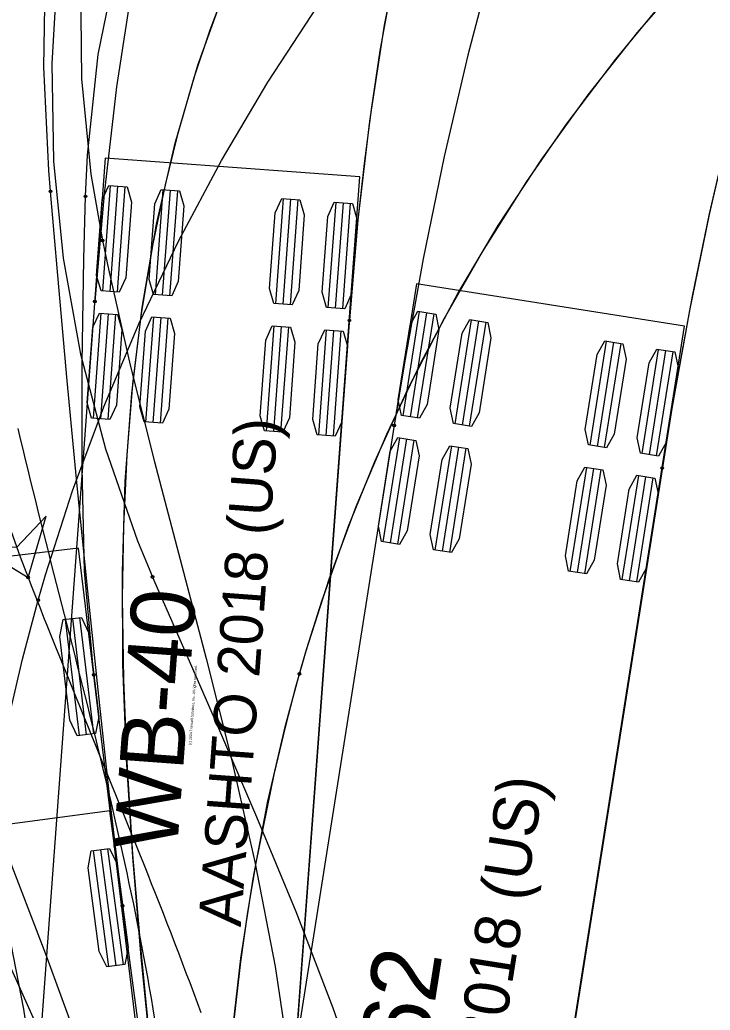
# Model space of a CAD drawing. Extents: x 1600240 to 1604759, y 285789 to 289704.
# Drawn here: x 1601627.09 to 1601648.72, y 286639.24 to 286670.26 of the extents above; entities that cross this region are included whole.
import ezdxf

# ---------------------------------------------------------------- set-up
doc = ezdxf.new("R2010")
doc.units = 0
for name, color, linetype in [('MT_P_CL_Double_Solid', 7, 'Continuous'), ('MT_X_Edge_Line', 7, 'Continuous'), ('TR_Turning_Path2', 7, 'Continuous'), ('TR_Turning_Path3', 7, 'Continuous'), ('TR_Turning_Path4', 7, 'Continuous')]:
    doc.layers.add(name, color=color, linetype=linetype)

msp = doc.modelspace()

# ---------------------------------------------------------------- linework, layer by layer
at = {"layer": 'MT_P_CL_Double_Solid'}
for p, q in [((1601629.914, 286645.489), (1601621.984, 286644.432)), ((1601630.904, 286638.054), (1601629.914, 286645.489)), ((1601629.386, 286644.241), (1601629.871, 286640.607)), ((1601629.613, 286644.272), (1601630.098, 286640.637)), ((1601629.84, 286644.302), (1601630.325, 286640.667))]:
    msp.add_line(p, q, dxfattribs=at)
for points in [[(1601628.052, 286664.891), (1601627.998, 286665.545), (1601627.842, 286668.782), (1601627.894, 286671.975), (1601628.19, 286675.107), (1601628.758, 286678.153), (1601629.625, 286681.081), (1601630.808, 286683.848), (1601632.315, 286686.434), (1601634.062, 286688.889), (1601636.008, 286691.19), (1601638.138, 286693.32), (1601640.439, 286695.265), (1601642.893, 286697.012), (1601645.484, 286698.549), (1601648.194, 286699.864), (1601651.004, 286700.949), (1601653.895, 286701.797), (1601656.846, 286702.4), (1601658.937, 286702.676)], [(1601632.426, 286627.244), (1601632.345, 286627.903), (1601631.948, 286631.194), (1601631.567, 286634.468), (1601631.211, 286637.711), (1601630.894, 286640.909), (1601630.63, 286644.047), (1601630.434, 286647.107), (1601630.321, 286650.076), (1601630.303, 286652.973), (1601630.392, 286655.803), (1601630.596, 286658.564), (1601630.923, 286661.252), (1601631.376, 286663.864), (1601631.958, 286666.395), (1601632.67, 286668.841), (1601633.512, 286671.196), (1601634.483, 286673.455), (1601635.579, 286675.612), (1601636.419, 286677.058)], [(1601633.596, 286671.411), (1601633.041, 286669.939), (1601632.543, 286668.446), (1601632.019, 286666.63), (1601631.64, 286665.099), (1601631.254, 286663.244), (1601630.894, 286661.06), (1601630.624, 286658.856), (1601630.44, 286656.637), (1601630.333, 286654.405), (1601630.297, 286652.164), (1601630.333, 286649.594), (1601630.438, 286647.019), (1601630.624, 286644.118), (1601630.866, 286641.217), (1601631.215, 286637.672), (1601631.642, 286633.807), (1601632.214, 286628.979), (1601633.671, 286617.403), (1601635.924, 286600.387), (1601627.995, 286599.33), (1601627.804, 286600.759)], [(1601630.31, 286642.515), (1601629.922, 286645.791), (1601629.563, 286649.081), (1601629.218, 286652.372), (1601628.89, 286655.664), (1601628.577, 286658.958), (1601628.279, 286662.253), (1601628.052, 286664.89)]]:
    msp.add_lwpolyline(points, dxfattribs=at)
msp.add_lwpolyline([(1601629.33, 286644.234), (1601629.897, 286644.309), (1601630.135, 286643.823), (1601630.484, 286641.206), (1601630.381, 286640.675), (1601629.814, 286640.599), (1601629.576, 286641.085), (1601629.227, 286643.702)], close=True, dxfattribs=at)
for centre in [(1601628.052, 286664.89), (1601628.052, 286664.891), (1601630.31, 286642.515)]:
    msp.add_circle(centre, 0.0417, dxfattribs=at)
at = {"layer": 'MT_X_Edge_Line'}
msp.add_arc((1602837.866, 287782.942), 1921, 229.7619, 229.7619, dxfattribs=at)
at = {"layer": 'TR_Turning_Path2'}
for p, q in [((1601629.768, 286665.929), (1601627.338, 286633.019)), ((1601637.747, 286665.34), (1601629.768, 286665.929)), ((1601635.316, 286632.43), (1601637.747, 286665.34)), ((1601629.691, 286661.774), (1601629.934, 286665.065)), ((1601629.92, 286661.757), (1601630.163, 286665.048)), ((1601630.148, 286661.74), (1601630.391, 286665.031)), ((1601631.337, 286661.652), (1601631.58, 286664.943)), ((1601631.565, 286661.635), (1601631.808, 286664.926)), ((1601631.794, 286661.618), (1601632.037, 286664.909)), ((1601635.11, 286661.373), (1601635.353, 286664.665)), ((1601635.338, 286661.357), (1601635.581, 286664.648)), ((1601635.567, 286661.34), (1601635.81, 286664.631)), ((1601636.755, 286661.252), (1601636.998, 286664.543)), ((1601636.984, 286661.235), (1601637.227, 286664.526)), ((1601637.212, 286661.218), (1601637.455, 286664.509)), ((1601629.397, 286657.784), (1601629.64, 286661.075)), ((1601629.625, 286657.768), (1601629.868, 286661.059)), ((1601629.854, 286657.751), (1601630.097, 286661.042)), ((1601631.042, 286657.663), (1601631.285, 286660.954)), ((1601631.271, 286657.646), (1601631.514, 286660.937)), ((1601631.499, 286657.629), (1601631.742, 286660.92)), ((1601634.815, 286657.384), (1601635.058, 286660.675)), ((1601635.044, 286657.367), (1601635.287, 286660.658)), ((1601635.272, 286657.351), (1601635.515, 286660.642)), ((1601636.461, 286657.263), (1601636.704, 286660.554)), ((1601636.689, 286657.246), (1601636.932, 286660.537)), ((1601636.918, 286657.229), (1601637.161, 286660.52))]:
    msp.add_line(p, q, dxfattribs=at)
for points in [[(1601660.811, 286703.245), (1601659.827, 286703.152), (1601656.594, 286702.738), (1601653.44, 286702.14), (1601650.384, 286701.326), (1601647.454, 286700.268), (1601644.684, 286698.947), (1601642.116, 286697.348), (1601639.799, 286695.471), (1601637.711, 286693.321), (1601635.814, 286690.989), (1601634.126, 286688.501), (1601632.661, 286685.877), (1601631.428, 286683.135), (1601630.438, 286680.297), (1601629.698, 286677.384), (1601629.213, 286674.418), (1601628.987, 286671.421), (1601629.021, 286668.415), (1601629.316, 286665.424), (1601629.676, 286663.351)], [(1601642.549, 286697.143), (1601641.961, 286696.515), (1601640.089, 286694.32), (1601638.357, 286691.963), (1601636.775, 286689.446), (1601635.349, 286686.773), (1601634.085, 286683.95), (1601632.985, 286680.993), (1601632.048, 286677.918), (1601631.267, 286674.746), (1601630.627, 286671.482), (1601630.119, 286668.166), (1601629.728, 286664.814), (1601629.437, 286661.441)], [(1601648.312, 286691.594), (1601647.84, 286691.09), (1601646.342, 286689.331), (1601644.957, 286687.442), (1601643.684, 286685.412), (1601642.524, 286683.234), (1601641.481, 286680.901), (1601640.559, 286678.416), (1601639.758, 286675.783), (1601639.076, 286673.011), (1601638.507, 286670.1), (1601638.047, 286667.089), (1601637.686, 286664.001), (1601637.415, 286660.852)], [(1601638.904, 286672.205), (1601638.371, 286669.291), (1601638.107, 286667.532), (1601637.879, 286665.767), (1601637.685, 286663.997), (1601637.473, 286661.627), (1601635.686, 286637.432)], [(1601621.785, 286664.025), (1601621.952, 286662.949), (1601622.604, 286659.411), (1601623.361, 286655.937), (1601624.18, 286652.522), (1601625.016, 286649.158), (1601625.826, 286645.835), (1601626.568, 286642.545), (1601627.202, 286639.282), (1601627.69, 286636.036), (1601628.097, 286632.743), (1601628.475, 286629.447), (1601628.824, 286626.147), (1601629.142, 286622.845)], [(1601629.677, 286663.347), (1601629.863, 286662.452), (1601630.549, 286659.447), (1601631.309, 286656.419), (1601632.111, 286653.36), (1601632.926, 286650.258), (1601633.718, 286647.104), (1601634.452, 286643.89), (1601635.091, 286640.609), (1601635.595, 286637.259), (1601636.013, 286633.896), (1601636.401, 286630.529), (1601636.759, 286627.159), (1601637.086, 286623.785)], [(1601627.026, 286657.463), (1601627.103, 286657.139), (1601627.181, 286656.815), (1601627.259, 286656.491), (1601627.338, 286656.167), (1601627.417, 286655.843), (1601627.497, 286655.519), (1601627.577, 286655.196), (1601627.658, 286654.872), (1601627.739, 286654.549), (1601627.82, 286654.226), (1601627.902, 286653.903), (1601627.983, 286653.579), (1601628.066, 286653.256), (1601628.148, 286652.933), (1601628.23, 286652.61), (1601628.313, 286652.287), (1601628.395, 286651.964), (1601628.478, 286651.642), (1601628.561, 286651.319), (1601628.643, 286650.996), (1601628.726, 286650.673), (1601628.808, 286650.35), (1601628.89, 286650.027), (1601628.972, 286649.704), (1601629.054, 286649.38), (1601629.135, 286649.057), (1601629.216, 286648.734), (1601629.297, 286648.41), (1601629.378, 286648.087), (1601629.458, 286647.763), (1601629.537, 286647.44), (1601629.616, 286647.116), (1601629.695, 286646.792), (1601629.772, 286646.468), (1601629.85, 286646.143), (1601629.926, 286645.819), (1601630.002, 286645.495), (1601630.077, 286645.17), (1601630.152, 286644.845), (1601630.225, 286644.52), (1601630.298, 286644.194), (1601630.37, 286643.869), (1601630.441, 286643.543), (1601630.51, 286643.217), (1601630.579, 286642.891), (1601630.647, 286642.565), (1601630.714, 286642.238), (1601630.779, 286641.911), (1601630.844, 286641.584), (1601630.907, 286641.257), (1601630.969, 286640.929), (1601631.03, 286640.602), (1601631.089, 286640.274), (1601631.147, 286639.945), (1601631.203, 286639.617), (1601631.258, 286639.288), (1601631.312, 286638.959)]]:
    msp.add_lwpolyline(points, dxfattribs=at)
for points in [[(1601630.205, 286661.736), (1601629.635, 286661.778), (1601629.497, 286662.251), (1601629.672, 286664.621), (1601629.878, 286665.069), (1601630.448, 286665.027), (1601630.586, 286664.553), (1601630.411, 286662.184)], [(1601631.851, 286661.614), (1601631.28, 286661.656), (1601631.142, 286662.13), (1601631.317, 286664.499), (1601631.523, 286664.947), (1601632.094, 286664.905), (1601632.231, 286664.432), (1601632.056, 286662.062)], [(1601635.624, 286661.336), (1601635.053, 286661.378), (1601634.915, 286661.851), (1601635.09, 286664.221), (1601635.296, 286664.669), (1601635.867, 286664.627), (1601636.004, 286664.153), (1601635.83, 286661.784)], [(1601637.269, 286661.214), (1601636.699, 286661.256), (1601636.561, 286661.73), (1601636.736, 286664.099), (1601636.942, 286664.547), (1601637.512, 286664.505), (1601637.65, 286664.032), (1601637.475, 286661.662)], [(1601629.91, 286657.747), (1601629.34, 286657.789), (1601629.202, 286658.262), (1601629.377, 286660.632), (1601629.583, 286661.08), (1601630.153, 286661.038), (1601630.291, 286660.564), (1601630.116, 286658.195)], [(1601631.556, 286657.625), (1601630.986, 286657.667), (1601630.848, 286658.141), (1601631.023, 286660.51), (1601631.229, 286660.958), (1601631.799, 286660.916), (1601631.937, 286660.443), (1601631.762, 286658.073)], [(1601635.329, 286657.346), (1601634.759, 286657.389), (1601634.621, 286657.862), (1601634.796, 286660.231), (1601635.002, 286660.68), (1601635.572, 286660.637), (1601635.71, 286660.164), (1601635.535, 286657.794)], [(1601636.975, 286657.225), (1601636.404, 286657.267), (1601636.266, 286657.74), (1601636.441, 286660.11), (1601636.647, 286660.558), (1601637.218, 286660.516), (1601637.355, 286660.042), (1601637.18, 286657.673)]]:
    msp.add_lwpolyline(points, close=True, dxfattribs=at)
for centre in [(1601629.676, 286663.351), (1601629.677, 286663.347), (1601629.437, 286661.441), (1601637.415, 286660.852)]:
    msp.add_circle(centre, 0.0417, dxfattribs=at)
msp.add_arc((1601663.616, 286670.316), 38.461, 132.7886, 189.9617, dxfattribs=at)
at = {"layer": 'TR_Turning_Path3'}
for p, q in [((1601628.933, 286653.719), (1601620.99, 286652.766)), ((1601630.72, 286638.826), (1601628.933, 286653.719)), ((1601628.509, 286651.486), (1601628.945, 286647.845)), ((1601628.736, 286651.513), (1601629.173, 286647.873)), ((1601628.964, 286651.541), (1601629.4, 286647.9))]:
    msp.add_line(p, q, dxfattribs=at)
for points in [[(1601629.148, 286664.736), (1601629.206, 286666.02), (1601629.542, 286669.177), (1601630.17, 286672.247), (1601631.112, 286675.193), (1601632.383, 286677.973), (1601633.977, 286680.587), (1601635.765, 286683.101), (1601637.713, 286685.494), (1601639.812, 286687.755), (1601642.053, 286689.876), (1601644.427, 286691.846), (1601646.923, 286693.658), (1601649.532, 286695.305), (1601652.242, 286696.778), (1601655.042, 286698.073), (1601657.92, 286699.184), (1601659.975, 286699.849)], [(1601627.668, 286652.089), (1601627.898, 286652.878), (1601628.745, 286655.51), (1601629.722, 286658.144), (1601630.832, 286660.764), (1601632.06, 286663.335), (1601633.404, 286665.852), (1601634.861, 286668.308), (1601636.429, 286670.7), (1601638.103, 286673.022), (1601639.88, 286675.269), (1601641.756, 286677.437), (1601642.338, 286678.072)], [(1601635.849, 286649.781), (1601636.049, 286650.467), (1601636.783, 286652.747), (1601637.629, 286655.024), (1601638.59, 286657.29), (1601639.653, 286659.516), (1601640.819, 286661.695), (1601642.083, 286663.824), (1601643.443, 286665.898), (1601644.896, 286667.913), (1601646.44, 286669.864), (1601648.071, 286671.747), (1601648.576, 286672.298)], [(1601647.044, 286670.583), (1601645.758, 286669.027), (1601644.212, 286666.991), (1601642.968, 286665.199), (1601641.626, 286663.083), (1601640.383, 286660.911), (1601639.242, 286658.688), (1601638.204, 286656.418), (1601637.382, 286654.396), (1601636.544, 286652.046), (1601636.075, 286650.558), (1601635.729, 286649.358), (1601635.41, 286648.15), (1601635.045, 286646.629), (1601634.486, 286643.863), (1601634.227, 286642.313), (1601634.002, 286640.755), (1601633.683, 286637.93)], [(1601629.41, 286649.748), (1601629.118, 286652.993), (1601629.042, 286656.238), (1601629.042, 286659.507), (1601629.093, 286662.775), (1601629.148, 286664.736)], [(1601626.64, 286603.897), (1601626.494, 286605.221), (1601626.143, 286608.515), (1601625.815, 286611.777), (1601625.519, 286614.992), (1601625.264, 286618.142), (1601625.059, 286621.219), (1601624.908, 286624.272), (1601624.821, 286627.304), (1601624.807, 286630.308), (1601624.871, 286633.282), (1601625.02, 286636.221), (1601625.259, 286639.119), (1601625.591, 286641.974), (1601626.019, 286644.782), (1601626.545, 286647.537), (1601627.171, 286650.235), (1601627.668, 286652.089)], [(1601635.088, 286604.837), (1601634.944, 286606.147), (1601634.597, 286609.397), (1601634.275, 286612.598), (1601633.987, 286615.732), (1601633.74, 286618.778), (1601633.544, 286621.724), (1601633.401, 286624.616), (1601633.32, 286627.459), (1601633.307, 286630.252), (1601633.366, 286632.99), (1601633.503, 286635.672), (1601633.719, 286638.296), (1601634.017, 286640.86), (1601634.399, 286643.36), (1601634.865, 286645.796), (1601635.415, 286648.164), (1601635.849, 286649.781)]]:
    msp.add_lwpolyline(points, dxfattribs=at)
msp.add_lwpolyline([(1601628.452, 286651.479), (1601629.02, 286651.547), (1601629.252, 286651.058), (1601629.567, 286648.437), (1601629.457, 286647.907), (1601628.889, 286647.839), (1601628.657, 286648.328), (1601628.342, 286650.949)], close=True, dxfattribs=at)
for centre in [(1601629.148, 286664.736), (1601629.148, 286664.736), (1601627.668, 286652.089), (1601627.668, 286652.089), (1601629.41, 286649.748), (1601635.849, 286649.781), (1601635.849, 286649.781)]:
    msp.add_circle(centre, 0.0417, dxfattribs=at)
at = {"layer": 'TR_Turning_Path4'}
for p, q in [((1601639.524, 286661.999), (1601632.03, 286614.588)), ((1601647.919, 286660.672), (1601639.524, 286661.999)), ((1601639.102, 286657.864), (1601639.617, 286661.124)), ((1601639.329, 286657.828), (1601639.844, 286661.088)), ((1601639.555, 286657.793), (1601640.07, 286661.052)), ((1601640.732, 286657.607), (1601641.247, 286660.866)), ((1601640.958, 286657.571), (1601641.473, 286660.83)), ((1601641.185, 286657.535), (1601641.7, 286660.794)), ((1601640.426, 286613.261), (1601647.919, 286660.672)), ((1601644.963, 286656.938), (1601645.478, 286660.197)), ((1601645.189, 286656.902), (1601645.704, 286660.162)), ((1601645.415, 286656.866), (1601645.931, 286660.126)), ((1601646.593, 286656.68), (1601647.108, 286659.94)), ((1601646.819, 286656.644), (1601647.334, 286659.904)), ((1601647.045, 286656.609), (1601647.56, 286659.868)), ((1601638.478, 286653.913), (1601638.993, 286657.173)), ((1601638.704, 286653.877), (1601639.219, 286657.137)), ((1601638.93, 286653.842), (1601639.446, 286657.101)), ((1601640.108, 286653.656), (1601640.623, 286656.915)), ((1601640.334, 286653.62), (1601640.849, 286656.879)), ((1601640.56, 286653.584), (1601641.075, 286656.844)), ((1601644.338, 286652.987), (1601644.854, 286656.246)), ((1601644.565, 286652.951), (1601645.08, 286656.211)), ((1601644.791, 286652.915), (1601645.306, 286656.175)), ((1601645.968, 286652.729), (1601646.483, 286655.989)), ((1601646.194, 286652.694), (1601646.71, 286655.953)), ((1601646.421, 286652.658), (1601646.936, 286655.917))]:
    msp.add_line(p, q, dxfattribs=at)
for points in [[(1601655.9, 286701.017), (1601655.249, 286700.932), (1601652.054, 286700.383), (1601648.952, 286699.599), (1601645.973, 286698.555), (1601643.153, 286697.233), (1601640.532, 286695.622), (1601638.159, 286693.721), (1601636.087, 286691.542), (1601634.319, 286689.088), (1601632.751, 286686.463), (1601631.398, 286683.721), (1601630.267, 286680.88), (1601629.365, 286677.958), (1601628.699, 286674.974), (1601628.272, 286671.946), (1601628.088, 286668.894), (1601628.146, 286665.837), (1601628.447, 286662.795), (1601628.99, 286659.786), (1601629.77, 286656.83), (1601630.782, 286653.945), (1601631.251, 286652.815)], [(1601659.26, 286700.748), (1601658.196, 286699.887), (1601656.467, 286698.359), (1601654.795, 286696.709), (1601653.181, 286694.925), (1601651.628, 286692.996), (1601650.139, 286690.916), (1601648.72, 286688.678), (1601647.378, 286686.284), (1601646.118, 286683.74), (1601644.942, 286681.048), (1601643.852, 286678.222), (1601642.853, 286675.285), (1601641.945, 286672.256), (1601641.125, 286669.152), (1601640.388, 286665.986), (1601639.729, 286662.772), (1601639.142, 286659.52), (1601638.821, 286657.554)], [(1601664.49, 286694.047), (1601663.633, 286693.353), (1601662.25, 286692.13), (1601660.918, 286690.813), (1601659.63, 286689.388), (1601658.383, 286687.838), (1601657.176, 286686.148), (1601656.009, 286684.306), (1601654.888, 286682.303), (1601653.817, 286680.137), (1601652.798, 286677.805), (1601651.839, 286675.313), (1601650.946, 286672.686), (1601650.124, 286669.941), (1601649.372, 286667.095), (1601648.69, 286664.163), (1601648.074, 286661.158), (1601647.521, 286658.092), (1601647.217, 286656.227)], [(1601650.815, 286672.273), (1601649.936, 286669.265), (1601649.283, 286666.736), (1601648.694, 286664.185), (1601648.162, 286661.611), (1601647.588, 286658.487), (1601641.451, 286619.743), (1601641.459, 286619.408), (1601641.753, 286616.075), (1601642.003, 286612.737), (1601642.209, 286609.396)], [(1601633.274, 286609.024), (1601632.925, 286614.317), (1601632.001, 286614.903), (1601631.529, 286619.515), (1601630.934, 286624.445), (1601630.251, 286629.364), (1601629.486, 286634.272), (1601629.385, 286634.594), (1601628.995, 286635.549), (1601627.777, 286638.407), (1601623.954, 286646.917), (1601622.636, 286649.946), (1601621.746, 286652.27), (1601621.22, 286653.841), (1601620.863, 286655.029), (1601620.437, 286656.624), (1601619.982, 286658.634), (1601619.616, 286660.656), (1601619.338, 286662.689), (1601619.149, 286664.727), (1601619.047, 286666.768), (1601619.034, 286668.807), (1601619.108, 286670.841)], [(1601627.346, 286652.799), (1601627.91, 286654.718), (1601626.986, 286653.732), (1601625.638, 286653.84), (1601627.346, 286652.799)], [(1601623.417, 286652.845), (1601624.145, 286650.831), (1601625.393, 286647.518), (1601626.656, 286644.247), (1601627.896, 286641.005), (1601629.077, 286637.784), (1601630.163, 286634.572), (1601631.117, 286631.362), (1601631.903, 286628.152), (1601632.485, 286624.944), (1601632.872, 286621.697), (1601633.201, 286618.417), (1601633.487, 286615.134), (1601633.729, 286611.847), (1601633.927, 286608.557), (1601634.08, 286605.264), (1601634.19, 286601.971), (1601634.255, 286598.675), (1601634.274, 286596.698)], [(1601627.346, 286652.799), (1601627.468, 286652.489), (1601627.589, 286652.178), (1601627.712, 286651.868), (1601627.835, 286651.558), (1601627.958, 286651.249), (1601628.082, 286650.939), (1601628.206, 286650.63), (1601628.33, 286650.32), (1601628.455, 286650.011), (1601628.579, 286649.702), (1601628.705, 286649.393), (1601628.83, 286649.084), (1601628.955, 286648.776), (1601629.081, 286648.467), (1601629.207, 286648.158), (1601629.333, 286647.849), (1601629.458, 286647.541), (1601629.584, 286647.232), (1601629.71, 286646.923), (1601629.836, 286646.615), (1601629.962, 286646.306), (1601630.088, 286645.997), (1601630.213, 286645.689), (1601630.338, 286645.38), (1601630.464, 286645.071), (1601630.589, 286644.762), (1601630.713, 286644.453), (1601630.838, 286644.143), (1601630.962, 286643.834), (1601631.085, 286643.524), (1601631.209, 286643.215), (1601631.332, 286642.905), (1601631.454, 286642.595), (1601631.576, 286642.285), (1601631.698, 286641.974), (1601631.819, 286641.664), (1601631.939, 286641.353), (1601632.059, 286641.042), (1601632.178, 286640.73), (1601632.296, 286640.419), (1601632.414, 286640.107), (1601632.531, 286639.795), (1601632.647, 286639.482), (1601632.762, 286639.17)], [(1601631.252, 286652.811), (1601631.998, 286651.098), (1601633.256, 286648.219), (1601634.51, 286645.304), (1601635.734, 286642.34), (1601636.901, 286639.314), (1601637.979, 286636.214), (1601638.936, 286633.033), (1601639.738, 286629.768), (1601640.346, 286626.419), (1601640.756, 286623.029), (1601641.102, 286619.645), (1601641.404, 286616.257), (1601641.66, 286612.865), (1601641.87, 286609.469), (1601642.035, 286606.072), (1601642.155, 286602.672), (1601642.229, 286599.27), (1601642.252, 286597.229)]]:
    msp.add_lwpolyline(points, dxfattribs=at)
for points in [[(1601639.611, 286657.784), (1601639.046, 286657.873), (1601638.948, 286658.356), (1601639.319, 286660.703), (1601639.561, 286661.133), (1601640.126, 286661.043), (1601640.224, 286660.56), (1601639.853, 286658.213)], [(1601641.241, 286657.526), (1601640.676, 286657.615), (1601640.578, 286658.099), (1601640.949, 286660.445), (1601641.191, 286660.875), (1601641.756, 286660.786), (1601641.854, 286660.302), (1601641.483, 286657.956)], [(1601645.472, 286656.857), (1601644.907, 286656.947), (1601644.809, 286657.43), (1601645.179, 286659.777), (1601645.422, 286660.206), (1601645.987, 286660.117), (1601646.085, 286659.634), (1601645.714, 286657.287)], [(1601647.101, 286656.6), (1601646.536, 286656.689), (1601646.438, 286657.172), (1601646.809, 286659.519), (1601647.052, 286659.949), (1601647.617, 286659.859), (1601647.715, 286659.376), (1601647.344, 286657.029)], [(1601638.987, 286653.833), (1601638.422, 286653.922), (1601638.324, 286654.405), (1601638.694, 286656.752), (1601638.937, 286657.182), (1601639.502, 286657.092), (1601639.6, 286656.609), (1601639.229, 286654.262)], [(1601640.616, 286653.575), (1601640.051, 286653.664), (1601639.953, 286654.148), (1601640.324, 286656.495), (1601640.567, 286656.924), (1601641.132, 286656.835), (1601641.23, 286656.351), (1601640.859, 286654.005)], [(1601644.847, 286652.906), (1601644.282, 286652.996), (1601644.184, 286653.479), (1601644.555, 286655.826), (1601644.797, 286656.255), (1601645.362, 286656.166), (1601645.46, 286655.683), (1601645.09, 286653.336)], [(1601646.477, 286652.649), (1601645.912, 286652.738), (1601645.814, 286653.221), (1601646.185, 286655.568), (1601646.427, 286655.998), (1601646.992, 286655.908), (1601647.09, 286655.425), (1601646.719, 286653.078)], [(1601627.346, 286652.799), (1601627.91, 286654.718), (1601626.986, 286653.732), (1601625.638, 286653.84)]]:
    msp.add_lwpolyline(points, close=True, dxfattribs=at)
for centre in [(1601638.821, 286657.554), (1601647.217, 286656.227), (1601627.346, 286652.799), (1601627.346, 286652.799), (1601631.251, 286652.815), (1601631.252, 286652.811)]:
    msp.add_circle(centre, 0.0417, dxfattribs=at)
msp.add_arc((1601666.506, 286668.102), 42.044, 142.5256, 201.3451, dxfattribs=at)

# ---------------------------------------------------------------- texts
at = {"layer": 'TR_Turning_Path2'}
for s, height, p in [('AASHTO 2018 (US)', 1.33333, (1601634.012, 286641.837)), ('WB-40', 2, (1601632.015, 286644.205)), ('(c) 2024 Transoft Solutions, Inc. All rights reserved.', 0.08, (1601632.462, 286647.543))]:
    msp.add_text(s, height=height, rotation=85.7767, dxfattribs=at).set_placement(p)
at = {"layer": 'TR_Turning_Path4'}
for s, height, p in [('AASHTO 2018 (US)', 1.41667, (1601640.884, 286629.726)), ('WB-62', 2.125, (1601638.978, 286632.409))]:
    msp.add_text(s, height=height, rotation=81.0186, dxfattribs=at).set_placement(p)

doc.saveas('drawing.dxf')
